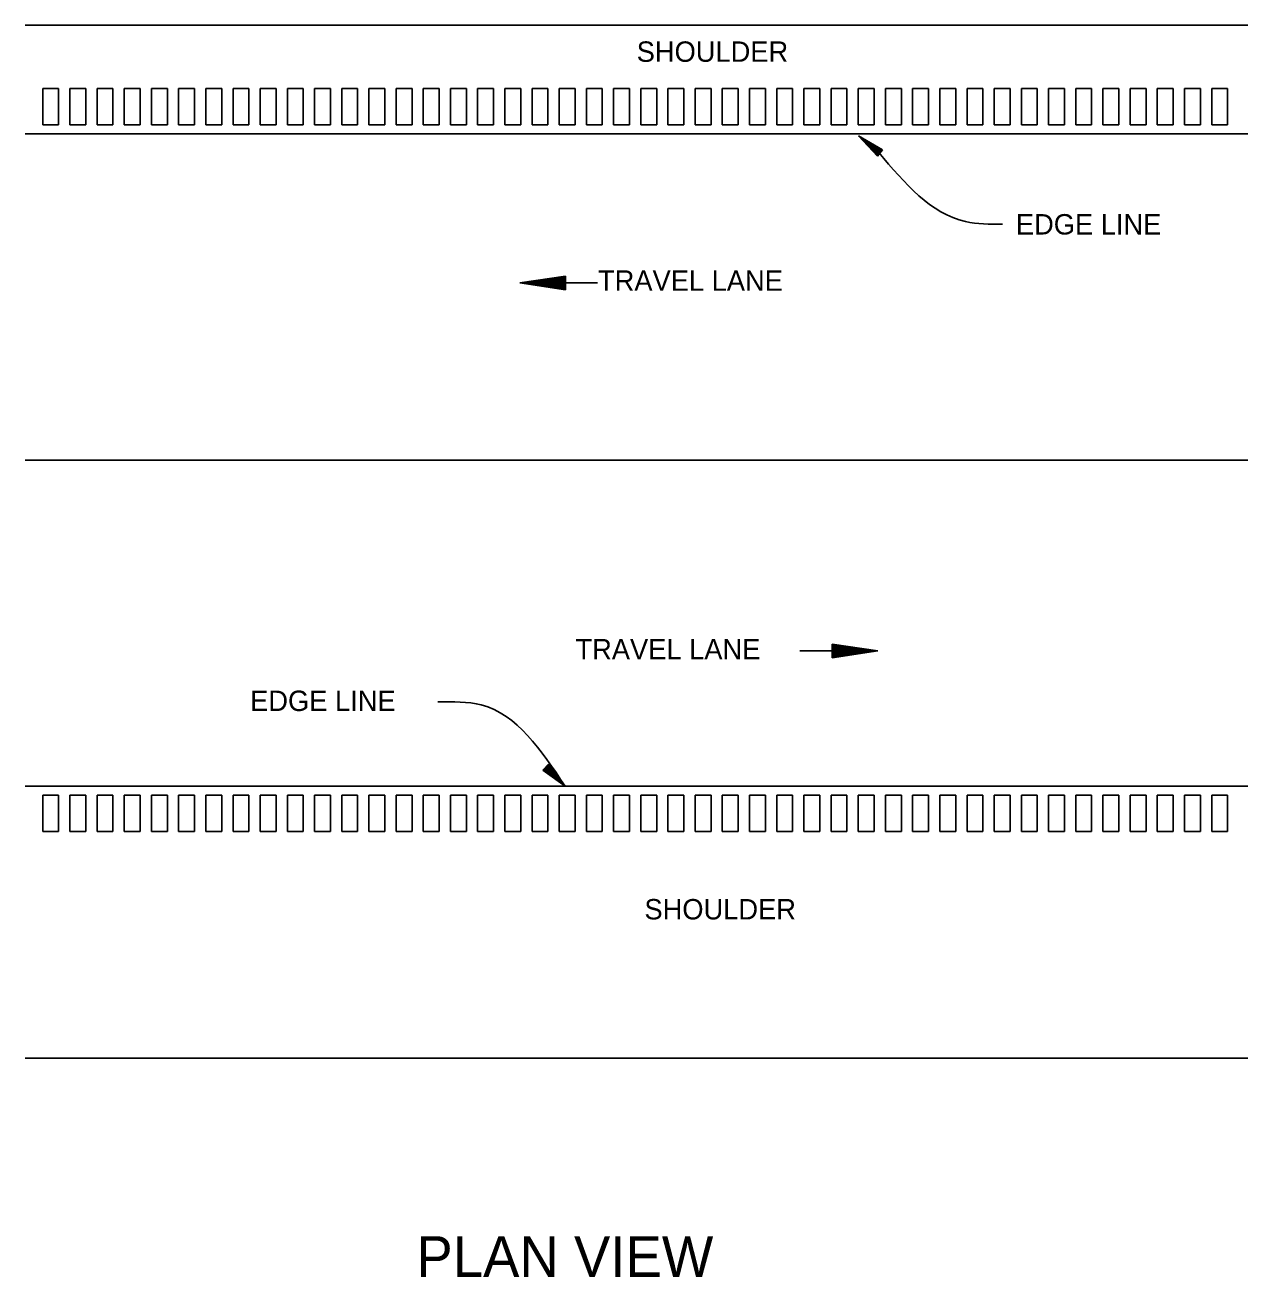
# Model space of a CAD drawing. Extents: x 634177 to 635904, y 289936 to 290970.
# Drawn here: x 635630.47 to 635666.46, y 290662.86 to 290699.7 of the extents above; entities that cross this region are included whole.
import ezdxf

# ---------------------------------------------------------------- set-up
doc = ezdxf.new("R2010")
doc.units = 0
doc.layers.add('Default', color=7, linetype='Continuous')

msp = doc.modelspace()

# ---------------------------------------------------------------- linework, layer by layer
at = {"layer": 'Default'}
for p, q in [((635630.47, 290699.703), (635666.459, 290699.703)), ((635630.99, 290696.769), (635630.99, 290697.833)), ((635630.99, 290697.833), (635631.458, 290697.833)), ((635631.458, 290696.769), (635631.458, 290697.833)), ((635631.79, 290696.769), (635631.79, 290697.833)), ((635631.79, 290697.833), (635632.258, 290697.833)), ((635632.258, 290696.769), (635632.258, 290697.833)), ((635632.59, 290696.769), (635632.59, 290697.833)), ((635632.59, 290697.833), (635633.058, 290697.833)), ((635633.058, 290696.769), (635633.058, 290697.833)), ((635633.39, 290696.769), (635633.39, 290697.833)), ((635633.39, 290697.833), (635633.858, 290697.833)), ((635633.858, 290696.769), (635633.858, 290697.833)), ((635634.19, 290696.769), (635634.19, 290697.833)), ((635634.19, 290697.833), (635634.658, 290697.833)), ((635634.658, 290696.769), (635634.658, 290697.833)), ((635634.99, 290696.769), (635634.99, 290697.833)), ((635634.99, 290697.833), (635635.458, 290697.833)), ((635635.458, 290696.769), (635635.458, 290697.833)), ((635635.79, 290696.769), (635635.79, 290697.833)), ((635635.79, 290697.833), (635636.258, 290697.833)), ((635636.258, 290696.769), (635636.258, 290697.833)), ((635636.59, 290696.769), (635636.59, 290697.833)), ((635636.59, 290697.833), (635637.058, 290697.833)), ((635637.058, 290696.769), (635637.058, 290697.833)), ((635637.39, 290696.769), (635637.39, 290697.833)), ((635637.39, 290697.833), (635637.858, 290697.833)), ((635637.858, 290696.769), (635637.858, 290697.833)), ((635638.19, 290696.769), (635638.19, 290697.833)), ((635638.19, 290697.833), (635638.658, 290697.833)), ((635638.658, 290696.769), (635638.658, 290697.833)), ((635638.99, 290696.769), (635638.99, 290697.833)), ((635638.99, 290697.833), (635639.458, 290697.833)), ((635639.458, 290696.769), (635639.458, 290697.833)), ((635639.79, 290696.769), (635639.79, 290697.833)), ((635639.79, 290697.833), (635640.258, 290697.833)), ((635640.258, 290696.769), (635640.258, 290697.833)), ((635640.59, 290696.769), (635640.59, 290697.833)), ((635640.59, 290697.833), (635641.058, 290697.833)), ((635641.058, 290696.769), (635641.058, 290697.833)), ((635641.39, 290696.769), (635641.39, 290697.833)), ((635641.39, 290697.833), (635641.858, 290697.833)), ((635641.858, 290696.769), (635641.858, 290697.833)), ((635642.19, 290696.769), (635642.19, 290697.833)), ((635642.19, 290697.833), (635642.658, 290697.833)), ((635642.658, 290696.769), (635642.658, 290697.833)), ((635642.99, 290696.769), (635642.99, 290697.833)), ((635642.99, 290696.769), (635642.99, 290697.833)), ((635642.99, 290697.833), (635643.458, 290697.833)), ((635643.458, 290696.769), (635643.458, 290697.833)), ((635643.79, 290696.769), (635643.79, 290697.833)), ((635643.79, 290697.833), (635644.258, 290697.833)), ((635644.258, 290696.769), (635644.258, 290697.833)), ((635644.59, 290696.769), (635644.59, 290697.833)), ((635644.59, 290697.833), (635645.058, 290697.833)), ((635645.058, 290696.769), (635645.058, 290697.833)), ((635645.39, 290696.769), (635645.39, 290697.833)), ((635645.39, 290697.833), (635645.858, 290697.833)), ((635645.858, 290696.769), (635645.858, 290697.833)), ((635646.19, 290696.769), (635646.19, 290697.833)), ((635646.19, 290697.833), (635646.658, 290697.833)), ((635646.658, 290696.769), (635646.658, 290697.833)), ((635646.99, 290696.769), (635646.99, 290697.833)), ((635646.99, 290697.833), (635647.458, 290697.833)), ((635647.458, 290696.769), (635647.458, 290697.833)), ((635647.79, 290696.769), (635647.79, 290697.833)), ((635647.79, 290697.833), (635648.258, 290697.833)), ((635648.258, 290696.769), (635648.258, 290697.833)), ((635648.59, 290696.769), (635648.59, 290697.833)), ((635648.59, 290697.833), (635649.058, 290697.833)), ((635649.058, 290696.769), (635649.058, 290697.833)), ((635649.39, 290696.769), (635649.39, 290697.833)), ((635649.39, 290697.833), (635649.858, 290697.833)), ((635649.858, 290696.769), (635649.858, 290697.833)), ((635650.19, 290696.769), (635650.19, 290697.833)), ((635650.19, 290697.833), (635650.658, 290697.833)), ((635650.658, 290696.769), (635650.658, 290697.833)), ((635650.99, 290696.769), (635650.99, 290697.833)), ((635650.99, 290697.833), (635651.458, 290697.833)), ((635651.458, 290696.769), (635651.458, 290697.833)), ((635651.79, 290696.769), (635651.79, 290697.833)), ((635651.79, 290697.833), (635652.258, 290697.833)), ((635652.258, 290696.769), (635652.258, 290697.833)), ((635652.59, 290696.769), (635652.59, 290697.833)), ((635652.59, 290697.833), (635653.058, 290697.833)), ((635653.058, 290696.769), (635653.058, 290697.833)), ((635653.39, 290696.769), (635653.39, 290697.833)), ((635653.39, 290697.833), (635653.858, 290697.833)), ((635653.858, 290696.769), (635653.858, 290697.833)), ((635654.19, 290696.769), (635654.19, 290697.833)), ((635654.19, 290697.833), (635654.658, 290697.833)), ((635654.658, 290696.769), (635654.658, 290697.833)), ((635654.99, 290696.769), (635654.99, 290697.833)), ((635654.99, 290697.833), (635655.458, 290697.833)), ((635655.458, 290696.769), (635655.458, 290697.833)), ((635655.79, 290696.769), (635655.79, 290697.833)), ((635655.79, 290697.833), (635656.258, 290697.833)), ((635656.258, 290696.769), (635656.258, 290697.833)), ((635656.59, 290696.769), (635656.59, 290697.833)), ((635656.59, 290697.833), (635657.058, 290697.833)), ((635657.058, 290696.769), (635657.058, 290697.833)), ((635657.39, 290696.769), (635657.39, 290697.833)), ((635657.39, 290697.833), (635657.859, 290697.833)), ((635657.859, 290696.769), (635657.859, 290697.833)), ((635658.191, 290696.769), (635658.191, 290697.833)), ((635658.191, 290697.833), (635658.659, 290697.833)), ((635658.659, 290696.769), (635658.659, 290697.833)), ((635658.991, 290696.769), (635658.991, 290697.833)), ((635658.991, 290697.833), (635659.459, 290697.833)), ((635659.459, 290696.769), (635659.459, 290697.833)), ((635659.791, 290696.769), (635659.791, 290697.833)), ((635659.791, 290697.833), (635660.259, 290697.833)), ((635660.259, 290696.769), (635660.259, 290697.833)), ((635660.591, 290696.769), (635660.591, 290697.833)), ((635660.591, 290697.833), (635661.059, 290697.833)), ((635661.059, 290696.769), (635661.059, 290697.833)), ((635661.391, 290696.769), (635661.391, 290697.833)), ((635661.391, 290697.833), (635661.859, 290697.833)), ((635661.859, 290696.769), (635661.859, 290697.833)), ((635662.191, 290696.769), (635662.191, 290697.833)), ((635662.191, 290697.833), (635662.659, 290697.833)), ((635662.659, 290696.769), (635662.659, 290697.833)), ((635662.991, 290696.769), (635662.991, 290697.833)), ((635662.991, 290697.833), (635663.459, 290697.833)), ((635663.459, 290696.769), (635663.459, 290697.833)), ((635663.791, 290696.769), (635663.791, 290697.833)), ((635663.791, 290697.833), (635664.259, 290697.833)), ((635664.259, 290696.769), (635664.259, 290697.833)), ((635664.591, 290696.769), (635664.591, 290697.833)), ((635664.591, 290697.833), (635665.059, 290697.833)), ((635665.059, 290696.769), (635665.059, 290697.833)), ((635665.391, 290696.769), (635665.391, 290697.833)), ((635665.391, 290697.833), (635665.859, 290697.833)), ((635665.859, 290696.769), (635665.859, 290697.833)), ((635631.458, 290696.769), (635630.99, 290696.769)), ((635632.258, 290696.769), (635631.79, 290696.769)), ((635633.058, 290696.769), (635632.59, 290696.769)), ((635633.858, 290696.769), (635633.39, 290696.769)), ((635634.658, 290696.769), (635634.19, 290696.769)), ((635635.458, 290696.769), (635634.99, 290696.769)), ((635636.258, 290696.769), (635635.79, 290696.769)), ((635637.058, 290696.769), (635636.59, 290696.769)), ((635637.858, 290696.769), (635637.39, 290696.769)), ((635638.658, 290696.769), (635638.19, 290696.769)), ((635639.458, 290696.769), (635638.99, 290696.769)), ((635640.258, 290696.769), (635639.79, 290696.769)), ((635641.058, 290696.769), (635640.59, 290696.769)), ((635641.858, 290696.769), (635641.39, 290696.769)), ((635642.658, 290696.769), (635642.19, 290696.769)), ((635643.458, 290696.769), (635642.99, 290696.769)), ((635644.258, 290696.769), (635643.79, 290696.769)), ((635645.058, 290696.769), (635644.59, 290696.769)), ((635645.858, 290696.769), (635645.39, 290696.769)), ((635646.658, 290696.769), (635646.19, 290696.769)), ((635647.458, 290696.769), (635646.99, 290696.769)), ((635648.258, 290696.769), (635647.79, 290696.769)), ((635649.058, 290696.769), (635648.59, 290696.769)), ((635649.858, 290696.769), (635649.39, 290696.769)), ((635650.658, 290696.769), (635650.19, 290696.769)), ((635651.458, 290696.769), (635650.99, 290696.769)), ((635652.258, 290696.769), (635651.79, 290696.769)), ((635653.058, 290696.769), (635652.59, 290696.769)), ((635653.858, 290696.769), (635653.39, 290696.769)), ((635654.658, 290696.769), (635654.19, 290696.769)), ((635655.458, 290696.769), (635654.99, 290696.769)), ((635656.258, 290696.769), (635655.79, 290696.769)), ((635657.058, 290696.769), (635656.59, 290696.769)), ((635657.859, 290696.769), (635657.39, 290696.769)), ((635658.659, 290696.769), (635658.191, 290696.769)), ((635659.459, 290696.769), (635658.991, 290696.769)), ((635660.259, 290696.769), (635659.791, 290696.769)), ((635661.059, 290696.769), (635660.591, 290696.769)), ((635661.859, 290696.769), (635661.391, 290696.769)), ((635662.659, 290696.769), (635662.191, 290696.769)), ((635663.459, 290696.769), (635662.991, 290696.769)), ((635664.259, 290696.769), (635663.791, 290696.769)), ((635665.059, 290696.769), (635664.591, 290696.769)), ((635665.859, 290696.769), (635665.391, 290696.769)), ((635630.47, 290696.503), (635648.38, 290696.503)), ((635666.459, 290696.503), (635648.38, 290696.503)), ((635655.552, 290695.847), (635655.002, 290696.441)), ((635655.702, 290696.035), (635655.002, 290696.441)), ((635655.564, 290695.863), (635655.106, 290696.357)), ((635655.69, 290696.019), (635655.106, 290696.357)), ((635655.676, 290696.003), (635655.214, 290696.273)), ((635655.578, 290695.879), (635655.214, 290696.273)), ((635655.59, 290695.895), (635655.318, 290696.189)), ((635655.664, 290695.987), (635655.318, 290696.189)), ((635655.65, 290695.971), (635655.424, 290696.103)), ((635655.602, 290695.911), (635655.424, 290696.103)), ((635655.638, 290695.955), (635655.528, 290696.021)), ((635655.614, 290695.927), (635655.528, 290696.021)), ((635655.552, 290695.847), (635655.702, 290696.035)), ((635646.372, 290692.317), (635645.028, 290692.115)), ((635646.372, 290692.283), (635645.252, 290692.115)), ((635646.372, 290692.251), (635645.482, 290692.115)), ((635646.372, 290692.215), (635645.704, 290692.115)), ((635646.372, 290692.179), (635645.934, 290692.115)), ((635646.372, 290692.149), (635646.158, 290692.115)), ((635646.372, 290692.317), (635646.372, 290691.915)), ((635647.316, 290692.115), (635645.028, 290692.115)), ((635646.372, 290691.915), (635645.028, 290692.115)), ((635646.372, 290691.947), (635645.252, 290692.115)), ((635646.372, 290691.983), (635645.482, 290692.115)), ((635646.372, 290692.015), (635645.704, 290692.115)), ((635646.372, 290692.049), (635645.934, 290692.115)), ((635646.372, 290692.083), (635646.158, 290692.115)), ((635630.47, 290686.903), (635666.459, 290686.903)), ((635654.218, 290681.483), (635655.562, 290681.285)), ((635654.218, 290681.083), (635654.218, 290681.483)), ((635654.218, 290681.451), (635655.338, 290681.285)), ((635653.274, 290681.285), (635655.562, 290681.285)), ((635654.218, 290681.417), (635655.108, 290681.285)), ((635654.218, 290681.383), (635654.886, 290681.285)), ((635654.218, 290681.349), (635654.656, 290681.285)), ((635654.218, 290681.317), (635654.432, 290681.285)), ((635654.218, 290681.083), (635655.562, 290681.285)), ((635654.218, 290681.219), (635654.656, 290681.285)), ((635654.218, 290681.149), (635655.108, 290681.285)), ((635654.218, 290681.115), (635655.338, 290681.285)), ((635654.218, 290681.183), (635654.886, 290681.285)), ((635654.218, 290681.251), (635654.432, 290681.285)), ((635645.87, 290677.952), (635645.704, 290677.78)), ((635645.704, 290677.78), (635646.362, 290677.308)), ((635645.718, 290677.794), (635646.266, 290677.402)), ((635645.732, 290677.808), (635646.166, 290677.498)), ((635645.746, 290677.822), (635646.072, 290677.59)), ((635645.76, 290677.836), (635645.974, 290677.684)), ((635645.774, 290677.852), (635645.878, 290677.778)), ((635645.8, 290677.878), (635645.878, 290677.778)), ((635645.814, 290677.892), (635645.974, 290677.684)), ((635645.828, 290677.908), (635646.072, 290677.59)), ((635645.842, 290677.922), (635646.166, 290677.498)), ((635645.856, 290677.936), (635646.266, 290677.402)), ((635645.87, 290677.952), (635646.362, 290677.308)), ((635630.47, 290677.302), (635648.38, 290677.302)), ((635631.458, 290677.036), (635630.99, 290677.036)), ((635630.99, 290677.036), (635630.99, 290675.972)), ((635631.458, 290677.036), (635631.458, 290675.972)), ((635632.258, 290677.036), (635631.79, 290677.036)), ((635631.79, 290677.036), (635631.79, 290675.972)), ((635632.258, 290677.036), (635632.258, 290675.972)), ((635633.058, 290677.036), (635632.59, 290677.036)), ((635632.59, 290677.036), (635632.59, 290675.972)), ((635633.058, 290677.036), (635633.058, 290675.972)), ((635633.858, 290677.036), (635633.39, 290677.036)), ((635633.39, 290677.036), (635633.39, 290675.972)), ((635633.858, 290677.036), (635633.858, 290675.972)), ((635634.658, 290677.036), (635634.19, 290677.036)), ((635634.19, 290677.036), (635634.19, 290675.972)), ((635634.658, 290677.036), (635634.658, 290675.972)), ((635635.458, 290677.036), (635634.99, 290677.036)), ((635634.99, 290677.036), (635634.99, 290675.972)), ((635635.458, 290677.036), (635635.458, 290675.972)), ((635636.258, 290677.036), (635635.79, 290677.036)), ((635635.79, 290677.036), (635635.79, 290675.972)), ((635636.258, 290677.036), (635636.258, 290675.972)), ((635637.058, 290677.036), (635636.59, 290677.036)), ((635636.59, 290677.036), (635636.59, 290675.972)), ((635637.058, 290677.036), (635637.058, 290675.972)), ((635637.858, 290677.036), (635637.39, 290677.036)), ((635637.39, 290677.036), (635637.39, 290675.972)), ((635637.858, 290677.036), (635637.858, 290675.972)), ((635638.658, 290677.036), (635638.19, 290677.036)), ((635638.19, 290677.036), (635638.19, 290675.972)), ((635638.658, 290677.036), (635638.658, 290675.972)), ((635639.458, 290677.036), (635638.99, 290677.036)), ((635638.99, 290677.036), (635638.99, 290675.972)), ((635639.458, 290677.036), (635639.458, 290675.972)), ((635640.258, 290677.036), (635639.79, 290677.036)), ((635639.79, 290677.036), (635639.79, 290675.972)), ((635640.258, 290677.036), (635640.258, 290675.972)), ((635641.058, 290677.036), (635640.59, 290677.036)), ((635640.59, 290677.036), (635640.59, 290675.972)), ((635641.058, 290677.036), (635641.058, 290675.972)), ((635641.858, 290677.036), (635641.39, 290677.036)), ((635641.39, 290677.036), (635641.39, 290675.972)), ((635641.858, 290677.036), (635641.858, 290675.972)), ((635642.658, 290677.036), (635642.19, 290677.036)), ((635642.19, 290677.036), (635642.19, 290675.972)), ((635642.658, 290677.036), (635642.658, 290675.972)), ((635643.458, 290677.036), (635642.99, 290677.036)), ((635642.99, 290677.036), (635642.99, 290675.972)), ((635643.458, 290677.036), (635643.458, 290675.972)), ((635644.258, 290677.036), (635643.79, 290677.036)), ((635643.79, 290677.036), (635643.79, 290675.972)), ((635644.258, 290677.036), (635644.258, 290675.972)), ((635645.058, 290677.036), (635644.59, 290677.036)), ((635644.59, 290677.036), (635644.59, 290675.972)), ((635645.058, 290677.036), (635645.058, 290675.972)), ((635645.858, 290677.036), (635645.39, 290677.036)), ((635645.39, 290677.036), (635645.39, 290675.972)), ((635645.858, 290677.036), (635645.858, 290675.972)), ((635646.658, 290677.036), (635646.19, 290677.036)), ((635646.19, 290677.036), (635646.19, 290675.972)), ((635646.658, 290677.036), (635646.658, 290675.972)), ((635647.458, 290677.036), (635646.99, 290677.036)), ((635646.99, 290677.036), (635646.99, 290675.972)), ((635647.458, 290677.036), (635647.458, 290675.972)), ((635648.258, 290677.036), (635647.79, 290677.036)), ((635647.79, 290677.036), (635647.79, 290675.972)), ((635648.258, 290677.036), (635648.258, 290675.972)), ((635666.459, 290677.302), (635648.38, 290677.302)), ((635649.058, 290677.036), (635648.59, 290677.036)), ((635648.59, 290677.036), (635648.59, 290675.972)), ((635649.058, 290677.036), (635649.058, 290675.972)), ((635649.858, 290677.036), (635649.39, 290677.036)), ((635649.39, 290677.036), (635649.39, 290675.972)), ((635649.858, 290677.036), (635649.858, 290675.972)), ((635650.658, 290677.036), (635650.19, 290677.036)), ((635650.19, 290677.036), (635650.19, 290675.972)), ((635650.658, 290677.036), (635650.658, 290675.972)), ((635651.458, 290677.036), (635650.99, 290677.036)), ((635650.99, 290677.036), (635650.99, 290675.972)), ((635651.458, 290677.036), (635651.458, 290675.972)), ((635652.258, 290677.036), (635651.79, 290677.036)), ((635651.79, 290677.036), (635651.79, 290675.972)), ((635652.258, 290677.036), (635652.258, 290675.972)), ((635653.058, 290677.036), (635652.59, 290677.036)), ((635652.59, 290677.036), (635652.59, 290675.972)), ((635653.058, 290677.036), (635653.058, 290675.972)), ((635653.858, 290677.036), (635653.39, 290677.036)), ((635653.39, 290677.036), (635653.39, 290675.972)), ((635653.858, 290677.036), (635653.858, 290675.972)), ((635654.658, 290677.036), (635654.19, 290677.036)), ((635654.19, 290677.036), (635654.19, 290675.972)), ((635654.658, 290677.036), (635654.658, 290675.972)), ((635655.458, 290677.036), (635654.99, 290677.036)), ((635654.99, 290677.036), (635654.99, 290675.972)), ((635655.458, 290677.036), (635655.458, 290675.972)), ((635656.258, 290677.036), (635655.79, 290677.036)), ((635655.79, 290677.036), (635655.79, 290675.972)), ((635656.258, 290677.036), (635656.258, 290675.972)), ((635657.058, 290677.036), (635656.59, 290677.036)), ((635656.59, 290677.036), (635656.59, 290675.972)), ((635657.058, 290677.036), (635657.058, 290675.972)), ((635657.859, 290677.036), (635657.39, 290677.036)), ((635657.39, 290677.036), (635657.39, 290675.972)), ((635657.671, 290677.302), (635666.459, 290677.302)), ((635657.859, 290677.036), (635657.859, 290675.972)), ((635658.659, 290677.036), (635658.191, 290677.036)), ((635658.191, 290677.036), (635658.191, 290675.972)), ((635658.659, 290677.036), (635658.659, 290675.972)), ((635659.459, 290677.036), (635658.991, 290677.036)), ((635658.991, 290677.036), (635658.991, 290675.972)), ((635659.459, 290677.036), (635659.459, 290675.972)), ((635660.259, 290677.036), (635659.791, 290677.036)), ((635659.791, 290677.036), (635659.791, 290675.972)), ((635660.259, 290677.036), (635660.259, 290675.972)), ((635661.059, 290677.036), (635660.591, 290677.036)), ((635660.591, 290677.036), (635660.591, 290675.972)), ((635661.059, 290677.036), (635661.059, 290675.972)), ((635661.859, 290677.036), (635661.391, 290677.036)), ((635661.391, 290677.036), (635661.391, 290675.972)), ((635661.859, 290677.036), (635661.859, 290675.972)), ((635662.659, 290677.036), (635662.191, 290677.036)), ((635662.191, 290677.036), (635662.191, 290675.972)), ((635662.659, 290677.036), (635662.659, 290675.972)), ((635663.459, 290677.036), (635662.991, 290677.036)), ((635662.991, 290677.036), (635662.991, 290675.972)), ((635663.459, 290677.036), (635663.459, 290675.972)), ((635664.259, 290677.036), (635663.791, 290677.036)), ((635663.791, 290677.036), (635663.791, 290675.972)), ((635664.259, 290677.036), (635664.259, 290675.972)), ((635665.059, 290677.036), (635664.591, 290677.036)), ((635664.591, 290677.036), (635664.591, 290675.972)), ((635665.059, 290677.036), (635665.059, 290675.972)), ((635665.859, 290677.036), (635665.391, 290677.036)), ((635665.391, 290677.036), (635665.391, 290675.972)), ((635665.859, 290677.036), (635665.859, 290675.972)), ((635630.99, 290675.972), (635631.458, 290675.972)), ((635631.79, 290675.972), (635632.258, 290675.972)), ((635632.59, 290675.972), (635633.058, 290675.972)), ((635633.39, 290675.972), (635633.858, 290675.972)), ((635634.19, 290675.972), (635634.658, 290675.972)), ((635634.99, 290675.972), (635635.458, 290675.972)), ((635635.79, 290675.972), (635636.258, 290675.972)), ((635636.59, 290675.972), (635637.058, 290675.972)), ((635637.39, 290675.972), (635637.858, 290675.972)), ((635638.19, 290675.972), (635638.658, 290675.972)), ((635638.99, 290675.972), (635639.458, 290675.972)), ((635639.79, 290675.972), (635640.258, 290675.972)), ((635640.59, 290675.972), (635641.058, 290675.972)), ((635641.39, 290675.972), (635641.858, 290675.972)), ((635642.19, 290675.972), (635642.658, 290675.972)), ((635642.99, 290675.972), (635643.458, 290675.972)), ((635643.79, 290675.972), (635644.258, 290675.972)), ((635644.59, 290675.972), (635645.058, 290675.972)), ((635645.39, 290675.972), (635645.858, 290675.972)), ((635646.19, 290675.972), (635646.658, 290675.972)), ((635646.99, 290675.972), (635647.458, 290675.972)), ((635647.79, 290675.972), (635648.258, 290675.972)), ((635648.59, 290675.972), (635649.058, 290675.972)), ((635649.39, 290675.972), (635649.858, 290675.972)), ((635650.19, 290675.972), (635650.658, 290675.972)), ((635650.99, 290675.972), (635651.458, 290675.972)), ((635651.79, 290675.972), (635652.258, 290675.972)), ((635652.59, 290675.972), (635653.058, 290675.972)), ((635653.39, 290675.972), (635653.858, 290675.972)), ((635654.19, 290675.972), (635654.658, 290675.972)), ((635654.99, 290675.972), (635655.458, 290675.972)), ((635655.79, 290675.972), (635656.258, 290675.972)), ((635656.59, 290675.972), (635657.058, 290675.972)), ((635657.39, 290675.972), (635657.859, 290675.972)), ((635658.191, 290675.972), (635658.659, 290675.972)), ((635658.991, 290675.972), (635659.459, 290675.972)), ((635659.791, 290675.972), (635660.259, 290675.972)), ((635660.591, 290675.972), (635661.059, 290675.972)), ((635661.391, 290675.972), (635661.859, 290675.972)), ((635662.191, 290675.972), (635662.659, 290675.972)), ((635662.991, 290675.972), (635663.459, 290675.972)), ((635663.791, 290675.972), (635664.259, 290675.972)), ((635664.591, 290675.972), (635665.059, 290675.972)), ((635665.391, 290675.972), (635665.859, 290675.972)), ((635630.47, 290669.302), (635666.459, 290669.302))]:
    msp.add_line(p, q, dxfattribs=at)
for points in [[(635659.231, 290693.841), (635658.147, 290693.919), (635655.598, 290695.949)], [(635642.622, 290679.784), (635643.896, 290679.696), (635646.362, 290677.308)]]:
    msp.add_spline(points, degree=3, dxfattribs=at)

# ---------------------------------------------------------------- texts
for s, height, p in [('SHOULDER', 0.6, (635648.47, 290698.621)), ('EDGE LINE', 0.6, (635659.629, 290693.539)), ('TRAVEL LANE', 0.60002, (635647.332, 290691.883)), ('TRAVEL LANE', 0.60002, (635646.669, 290681.035)), ('EDGE LINE', 0.6, (635637.094, 290679.517)), ('SHOULDER', 0.6, (635648.698, 290673.384)), ('PLAN VIEW ', 1.2, (635641.986, 290662.862))]:
    msp.add_text(s, height=height, dxfattribs=at).set_placement(p)

doc.saveas('drawing.dxf')
